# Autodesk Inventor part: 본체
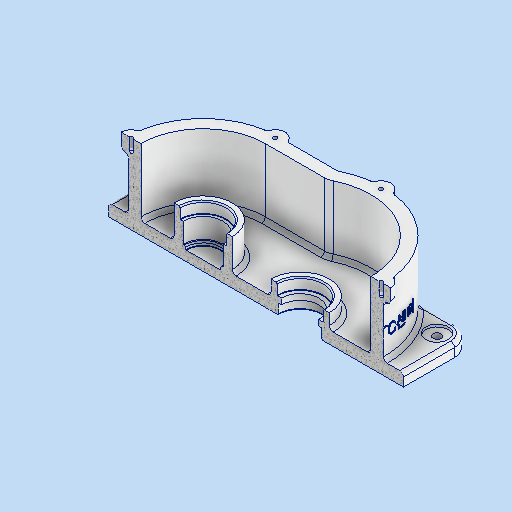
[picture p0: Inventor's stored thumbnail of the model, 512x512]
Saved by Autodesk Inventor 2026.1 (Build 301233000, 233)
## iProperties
Created: 2025-11
Part Number: 본체
Material: 알루미늄 6061
Document SubType Name: Modeling
Designer: PC-30
Density: 2.7 g/cm^3
Appearance: 알루미늄 - 평지
Mass: 1578.19 g
Surface Area: 1291.17 cm^2
Volume: 584.515 cm^3
Author: PC-30
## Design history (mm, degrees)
sketch "스케치1"
  geometry: L1 (-42.5, 60)-(5.684, 60); L2 (35.5, 67)-(35.5, -67); L3 (5.684, -60)-(-42.5, -60); L4 (-42.5, -60)-(-42.5, 60); L5 (-102.5, 0)-(102.5, 0); A1 r 60 centre (-42.5, 0) between (-42.5, 60) and (-42.5, -60); A2 r 67 centre (35.5, 0) between (5.684, -60) and (5.684, 60); 3 further points
  constraints: 10 end point, 8 point on circle, 4 midpoint, 2 centre point, 2 parallel, 1 coincident, 1 horizontal, 1 perpendicular, 1 tangent, 1 vertical alignment
  dimensions: "d0" = 60 radius of A1; "d1" = 67 radius of A2; "d2" = 78 distance of point (35.5, 0) A1.centre
extrude "돌출1" new body sketch "스케치1" distance "d3" = 64; taper "d4" = 0 deg
sketch "스케치2"
  geometry: L1 (5.684, 60)-(-42.5, 60) reference; L2 (-42.5, -60)-(5.684, -60) reference; L3 (-42.5, 50)-(8.132, 50); L4 (8.132, -50)-(-42.5, -50); A1 r 60 centre (-42.5, 0) between (-42.5, 60) and (-42.5, -60) reference; A2 r 67 centre (35.5, 0) between (5.684, -60) and (5.684, 60) reference; A3 r 57 centre (35.5, 0) between (8.132, -50) and (8.132, 50); A4 r 50 centre (-42.5, 0) between (-42.5, 50) and (-42.5, -50); 1 further point
  constraints: 4 end point, 4 point on circle, 2 centre point, 3 other
  dimensions: "d5" = 10 distance between parallel lines of L1 L3
extrude "돌출2" cut sketch "스케치2" distance "d6" = 54; taper "d7" = 0 deg
sketch "스케치3"
  geometry: L1 (118.5, 55)-(118.5, -55); L2 (-118.5, -55)-(-118.5, 55); L3 (5.684, 60)-(-42.5, 60) reference; L4 (-42.5, -60)-(5.684, -60) reference; L5 (-118.5, 55)-(-66.479, 55); L6 (73.762, 55)-(118.5, 55); L7 (118.5, -55)-(73.762, -55); L8 (-66.479, -55)-(-118.5, -55); A1 r 67 centre (35.5, 0) between (5.684, -60) and (5.684, 60) reference; A2 r 60 centre (-42.5, 0) between (-42.5, 60) and (-42.5, -60) reference; 2 further points
  constraints: 12 end point, 5 parallel, 4 point on circle, 2 horizontal, 2 perpendicular, 1 horizontal alignment, 1 midpoint
  dimensions: "d9" = 237 distance between parallel lines of L1 L2; "d10" = 154 distance from line of A1.centre L2; "d11" = 110 distance between parallel lines of L8 L5; "d12" = 110 distance between parallel lines of L7 L6; "d13" = 55 distance from line of L6 A1.centre
extrude "돌출3" join sketch "스케치3" distance "d14" = 10; taper "d15" = 0 deg
node "작업 평면1"
sketch "스케치4"
  geometry: A1 r 8 centre (-100.5, 0) between (-101.983, 7.861) and (-101.983, -7.861); A2 r 50 centre (-42.5, 0) between (-42.5, 50) and (-42.5, -50) reference; A3 r 60 centre (-42.5, 0) between (-42.5, 60) and (-42.5, -60) reference; 1 further point
  constraints: 4 point on circle, 1 centre point, 1 horizontal alignment
  dimensions: "d17" = 58 distance of A2.centre A1.centre; "d18" = 16 diameter of A1
extrude "돌출4" join sketch "스케치4" distance "d19" = 12; taper "d20" = 0 deg
sketch "스케치5"
  geometry: A1 r 8 centre (-100.5, 0) between (-101.983, 7.861) and (-101.983, -7.861) reference; 2 further points
  constraints: 1 coincident
hole "구멍1" sketch "스케치5" at (-100.5, 0) diameter "d21" = 3.242; stored, may be unused: countersink angle "d25" = 90 deg, drill point angle "d27" = 118 deg; dims "d22" = 8, "d23" = 37, "d24" = 9, "d26" = 10
sketch "스케치6"
  geometry: A1 r 67 centre (35.5, 0) between (5.684, -60) and (5.684, 60) reference; A2 r 57 centre (35.5, 0) between (8.132, -50) and (8.132, 50) reference; A3 r 8 centre (100.5, 0) between (102.038, -7.851) and (102.038, 7.851); 1 further point
  constraints: 4 point on circle, 1 centre point, 1 horizontal alignment
  dimensions: "d31" = 65 distance of A1.centre A3.centre; "d32" = 16 diameter of A3
extrude "돌출5" join sketch "스케치6" distance "d33" = 12; taper "d34" = 0 deg
sketch "스케치7"
  geometry: A1 r 8 centre (100.5, 0) between (102.038, -7.851) and (102.038, 7.851) reference; 2 further points
  constraints: 1 coincident
hole "구멍2" sketch "스케치7" at (100.5, 0) diameter "d35" = 3.242; stored, may be unused: countersink angle "d39" = 90 deg, drill point angle "d41" = 118 deg; dims "d36" = 8, "d37" = 4, "d38" = 2, "d40" = 10
sketch "스케치8"
  geometry: C1 r 23.5 at (-42.5, 0); A1 r 50 centre (-42.5, 0) between (-42.5, 50) and (-42.5, -50) reference; 1 further point
  constraints: 1 centre point, 1 concentric
  dimensions: "d45" = 47 diameter of C1
extrude "돌출6" join sketch "스케치8" distance "d46" = 26; taper "d47" = 0 deg
sketch "스케치9"
  geometry: C1 r 23.5 at (35.5, 0); A1 r 57 centre (35.5, 0) between (8.132, -50) and (8.132, 50) reference; 1 further point
  constraints: 1 centre point, 1 concentric
  dimensions: "d48" = 47 diameter of C1
extrude "돌출7" join sketch "스케치9" distance "d49" = 12; taper "d50" = 0 deg
sketch "스케치10"
  geometry: C1 r 23.5 at (0, 0) reference; 2 further points
  constraints: 1 coincident
hole "구멍3" sketch "스케치10" at (0, 0) diameter "d51" = 32; stored, may be unused: countersink angle "d55" = 90 deg, drill point angle "d57" = 0 deg; dims "d52" = 8, "d53" = 37, "d54" = 9, "d56" = 25
sketch "스케치11"
  geometry: C1 r 16 at (0, 0) reference; 2 further points
  constraints: 1 coincident
hole "구멍4" sketch "스케치11" at (0, 0) diameter "d58" = 28; stored, may be unused: countersink angle "d62" = 90 deg, drill point angle "d64" = 0 deg; dims "d59" = 6, "d60" = 37, "d61" = 9, "d63" = 3
sketch "스케치12"
  geometry: C1 r 23.5 at (0, 0) reference; 2 further points
  constraints: 1 coincident
hole "구멍5" sketch "스케치12" at (0, 0) diameter "d65" = 30; stored, may be unused: countersink angle "d69" = 90 deg, drill point angle "d71" = 0 deg; dims "d66" = 6, "d67" = 37, "d68" = 9, "d70" = 13.7
sketch "스케치13"
  geometry: C1 r 15 at (0, 0) reference; 2 further points
  constraints: 1 coincident
hole "구멍6" sketch "스케치13" at (0, 0) diameter "d72" = 35; stored, may be unused: countersink angle "d76" = 90 deg, drill point angle "d78" = 0 deg; dims "d73" = 6, "d74" = 37, "d75" = 9, "d77" = 8.3
chamfer "모따기1" distance "d79" = 1; stored, may be unused: second distance "d80" = 2, angle "d81" = 45 deg
chamfer "모따기2" distance "d82" = 0.8; stored, may be unused: second distance "d83" = 2, angle "d84" = 30 deg
chamfer "모따기3" distance "d85" = 1; stored, may be unused: second distance "d86" = 2, angle "d87" = 45 deg
chamfer "모따기4" distance "d88" = 1; stored, may be unused: second distance "d89" = 2, angle "d90" = 45 deg
fillet "모깎기1" dims "d91" = 0.3
fillet "모깎기2" dims "d92" = 0.3
fillet "모깎기3" dims "d93" = 0.3
fillet "모깎기4" dims "d94" = 13
fillet "모깎기5" dims "d95" = 3
fillet "모깎기6" dims "d96" = 3
fillet "모깎기7" dims "d97" = 3
fillet "모깎기8" dims "d98" = 14
sketch "스케치14"
  geometry: A1 r 14 centre (104.5, -41) between (104.5, -55) and (118.5, -41) reference; A2 r 14 centre (104.5, 41) between (118.5, 41) and (104.5, 55) reference; A3 r 14 centre (-104.5, 41) between (-104.5, 55) and (-118.5, 41) reference; A4 r 14 centre (-104.5, -41) between (-118.5, -41) and (-104.5, -55) reference; 5 further points
  constraints: 4 coincident
hole "구멍7" sketch "스케치14" at (104.5, -41), (104.5, 41), (-104.5, 41), (-104.5, -41) diameter "d99" = 6.6; stored, may be unused: countersink angle "d103" = 90 deg, drill point angle "d105" = 0 deg; dims "d100" = 6, "d101" = 18, "d102" = 2, "d104" = 8.3
fillet "모깎기9" dims "d106" = 3
fillet "모깎기10" dims "d107" = 3
fillet "모깎기11" dims "d108" = 3
node "작업 평면2"
sketch "스케치15"
  geometry: L1 (-39.451, 36.47)-(39.451, 36.47); L2 (39.451, 36.47)-(39.451, 23.53); L3 (39.451, 23.53)-(-39.451, 23.53); L4 (-39.451, 23.53)-(-39.451, 36.47); L5 (41, 0)-(-41, 0) reference; L6 (-39.451, 30)-(39.451, 30); L7 (0, 36.47)-(0, 23.53); 2 further points
  constraints: 5 midpoint, 4 end point, 1 vertical alignment, 2 other
  dimensions: "d110" = 30 distance between parallel lines of L5 L6
feature "엠보싱1" sketch "스케치15" dims "d5" = 10, "d111" = 0.5, "d112" = 0
fillet "모깎기12" dims "d113" = 3
node "솔리드1"
pattern_circular "원형 패턴1" dims "d29" = 180 deg
pattern_circular "원형 패턴2" dims "d43" = 180 deg
node "투영된 루프1"
node "투영된 루프2"
feature "A9D066F2-1C7D-4E18-AEED-F7BC21143FA4" dims "d51" = 32, "d52" = 8, "d53" = 37, "d54" = 9, "d55" = 90 deg, "d56" = 25, "d57" = 0
other parameters: "d16" = 0
